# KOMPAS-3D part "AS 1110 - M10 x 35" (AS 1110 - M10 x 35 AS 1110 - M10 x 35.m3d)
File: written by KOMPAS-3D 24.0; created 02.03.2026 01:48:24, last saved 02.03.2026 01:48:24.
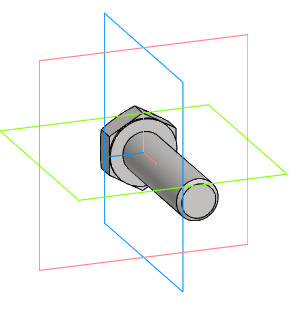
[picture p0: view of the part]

Document properties: Автор: R2D2; Полное имя файла: E:\Работа\Зайцев\GVWR3131M-2W-F-S Задвижка клиновая с выдвижным штоком DN.ru Ду50-200 Ру63\DN150\исходные материалы\AS 1110 - M10 x 35 AS 1110 - M10 x 35.m3d

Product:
- Body: Solid1  | qty 1
- Part/product: AS 1110 - M10 x 35
    Комментарий: Болты и винты   шестигранные точные   метрические ISO
    additional columns: Сталь, мягкая

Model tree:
1. Solid1  (labels: Solid1)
